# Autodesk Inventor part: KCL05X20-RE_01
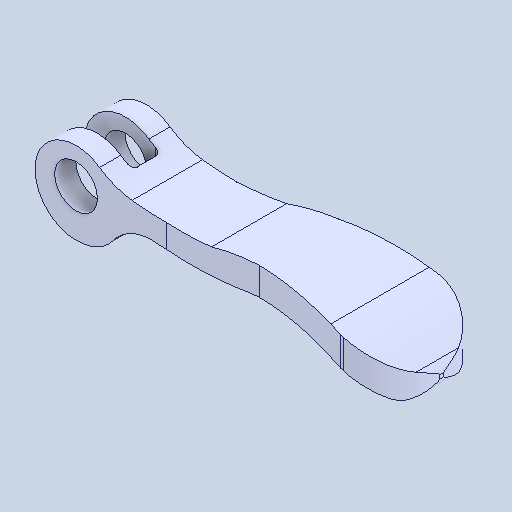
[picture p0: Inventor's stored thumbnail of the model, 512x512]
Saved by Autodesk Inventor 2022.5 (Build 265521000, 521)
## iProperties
Created: 2024-08
Part Number: KCL05X20-RE_01
Material: 一般
Document SubType Name: Modeling
Designer: ImaoCorp
Density: 1 g/cm^3
Appearance: 既定
Author: ImaoCorp
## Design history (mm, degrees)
feature "KCL05X20-RE_01"
node "ソリッド1"
